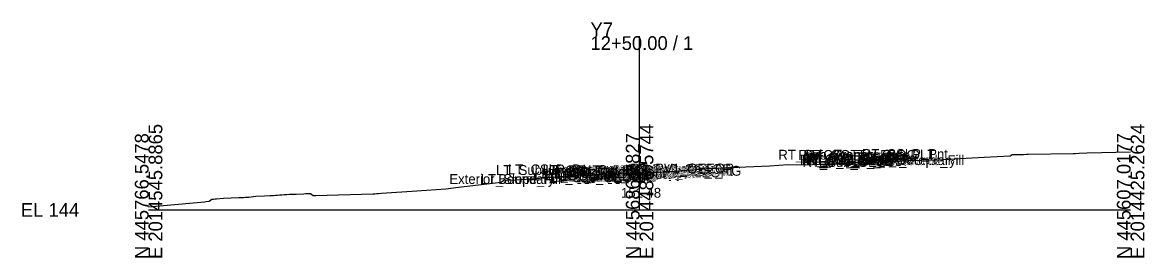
# Model space of a CAD drawing. Extents: x -26 to 203, y -10 to 7527.
# Drawn here: x -25.7 to 202.8, y 4990.3 to 5038.1 of the extents above; entities that cross this region are included whole.
import ezdxf

# ---------------------------------------------------------------- set-up
doc = ezdxf.new("R2010")
doc.units = 0
for name, color, linetype in [('Exist Cross Section Cell', 7, 'Continuous'), ('Exist XS Center Line Elevation Label', 7, 'Continuous'), ('Exist XS Ground Line', 7, 'Continuous'), ('Scratch_Level_0', 7, 'Continuous')]:
    doc.layers.add(name, color=color, linetype=linetype)

msp = doc.modelspace()

# ---------------------------------------------------------------- linework, layer by layer
at = {"layer": 'Exist Cross Section Cell'}
for p, q in [((100, 5000), (100, 5035.33)), ((0, 5000), (100, 5000)), ((100, 5000), (200, 5000))]:
    msp.add_line(p, q, dxfattribs=at)
at = {"layer": 'Exist XS Ground Line'}
msp.add_lwpolyline([(0, 5000.65), (11.37, 5001.67), (11.74, 5001.7), (12.36, 5001.76), (12.88, 5002.17), (13.2, 5002.21), (13.54, 5002.24), (13.86, 5002.28), (15.27, 5002.38), (18.41, 5002.5), (18.87, 5002.52), (19.3, 5002.54), (19.71, 5002.56), (20.09, 5002.57), (20.44, 5002.59), (21.84, 5002.77), (23.63, 5002.86), (24.73, 5002.9), (25.09, 5002.93), (25.47, 5002.96), (25.86, 5002.99), (26.27, 5003.02), (26.7, 5003.05), (27.16, 5003.08), (27.64, 5003.11), (28.16, 5003.14), (28.73, 5003.17), (29.35, 5003.2), (30.04, 5003.23), (31.62, 5003.28), (32.02, 5003.31), (32.96, 5003.33), (33.49, 5002.92), (34.04, 5002.92), (45.68, 5003.27), (46.1, 5003.3), (46.48, 5003.33), (46.82, 5003.35), (47.45, 5003.39), (54.66, 5003.87), (60.53, 5004.31), (63.09, 5004.6), (71.83, 5005.64), (72.37, 5006.04), (74.68, 5006.1), (77.99, 5006.34), (81.41, 5006.58), (86.76, 5007.05), (87.19, 5007.06), (97.9, 5007.41), (98.53, 5007.41), (98.92, 5007.42), (100, 5007.48), (108.28, 5007.95), (108.7, 5008.02), (114.65, 5008.43), (116.78, 5008.57), (126.49, 5008.96), (130.22, 5009.24), (133.81, 5009.17), (138.03, 5009.37), (139.13, 5009.36), (142.3, 5009.48), (152.08, 5009.95), (160.12, 5010.16), (160.49, 5010.18), (170.19, 5010.7), (175.46, 5011), (175.86, 5011.29), (176.89, 5011.24), (178.19, 5011.24), (178.79, 5011.31), (179.16, 5011.32), (188.27, 5011.45), (188.8, 5011.48), (189.53, 5011.51), (191.09, 5011.58), (200, 5011.78)], dxfattribs=at)

# ---------------------------------------------------------------- texts
at = {"layer": 'Exist Cross Section Cell'}
for s, p in [('Y7', (90, 5035.33)), ('12+50.00 / 1', (90, 5032.53)), ('EL 144', (-26, 4998.6))]:
    msp.add_text(s, height=2.8, dxfattribs=at).set_placement(p)
for s, p in [('E 2014545.8865', (2.8, 4990)), ('E 2014485.5744', (102.8, 4990)), ('E 2014425.2624', (202.8, 4990)), ('N 445766.5478', (0, 4990)), ('N 445686.7827', (100, 4990)), ('N 445607.0177', (200, 4990))]:
    msp.add_text(s, height=2.8, rotation=90, dxfattribs=at).set_placement(p)
at = {"layer": 'Exist XS Center Line Elevation Label'}
msp.add_text('151.48', height=2, dxfattribs=at).set_placement((96.2, 5002.48))
at = {"layer": 'Scratch_Level_0'}
for s, p in [('RT_Sub_Trench_Out_DLT', (128.26, 5010.22)), ('RT_CG_Top_Face', (132.34, 5010.18)), ('RT_CG_Top_BOC', (133.86, 5010.18)), ('RT_CSLP_Pnt', (145.25, 5010.37)), ('RT_PV1_OEEOP', (98.11, 5007.42)), ('RT_CG1_Shelf_Out', (132.63, 5009.23)), ('RT_CG_Bot_IE', (132.99, 5009.05)), ('RT_Sub_OEOT', (133.16, 5008.72)), ('RT_PV2_OEOT', (133.25, 5009.39)), ('RT_PV3_OEOT', (133.25, 5009.05)), ('RT_CG_Top_Gut', (133.31, 5009.68)), ('RT_PV1_OEOT', (133.82, 5009.64)), ('RT_CG_Bot_BOC', (133.89, 5009.2)), ('RT_Sub_OEOP', (136.5, 5008.92)), ('Exterior Boundary', (142.99, 5009.12)), ('RT_Slope_Fill', (149.32, 5009.12)), ('Exterior Boundary', (61.25, 5005.28)), ('LT_Slope_Fill', (67.63, 5005.28)), ('LT_Sub_Trench_Out_DLT', (70.75, 5007.1)), ('LT_CSLP_Pnt', (73.17, 5007.24)), ('LT_CG1_Shelf_Out', (78.55, 5005.99)), ('LT_PV_Sub_Tie_Out', (79.96, 5006.32)), ('LT_CG_Top_Face', (80.26, 5007.05)), ('LT_CG_Top_BOC', (80.78, 5007.05)), ('LT_CG_Bot_BOC', (80.81, 5006.02)), ('LT_CG_Top_Gut', (81.24, 5006.55)), ('LT_Sub_OEOP', (81.76, 5005.63)), ('LT_PV_OEEOP_EG', (82.54, 5006.32)), ('LT_Sub_OEEOP', (84.21, 5005.83)), ('LT_PV2_OEEOP', (84.31, 5006.5)), ('LT_PV3_OEEOP', (84.31, 5006.17)), ('LT_PV1_OEEOP', (84.87, 5006.62)), ('LT_CG_Bot_IE', (84.91, 5006.17)), ('LT_Sub_OEOT', (85.08, 5005.83)), ('LT_PV2_OEOT', (85.17, 5006.5)), ('LT_PV3_OEOT', (85.17, 5006.17)), ('LT_PV1_OEOT', (85.74, 5006.75)), ('RT_PV_IEEOP_EG', (88.14, 5006.48)), ('LT_PV_IEEOP_EG', (88.19, 5006.48)), ('RT_PV2_IEEOP', (89.91, 5006.8)), ('RT_PV3_IEEOP', (89.91, 5006.47)), ('LT_PV2_IEEOP', (89.95, 5006.8)), ('LT_PV3_IEEOP', (89.95, 5006.47)), ('RT_PV1_IEEOP', (90.47, 5006.92)), ('LT_PV1_IEEOP', (90.52, 5006.92)), ('RT_PV_Sub_Tie_Out', (93.16, 5006.95)), ('PV2_PGL', (93.91, 5006.8)), ('PV1_PGL', (94.47, 5007.05)), ('RT_PV_OEEOP_EG', (95.77, 5006.95)), ('RT_Sub_OEEOP', (97.44, 5006.63)), ('RT_PV2_OEEOP', (97.54, 5007.3)), ('RT_PV3_OEEOP', (97.54, 5006.96))]:
    msp.add_text(s, height=2, dxfattribs=at).set_placement(p)

doc.saveas('drawing.dxf')
